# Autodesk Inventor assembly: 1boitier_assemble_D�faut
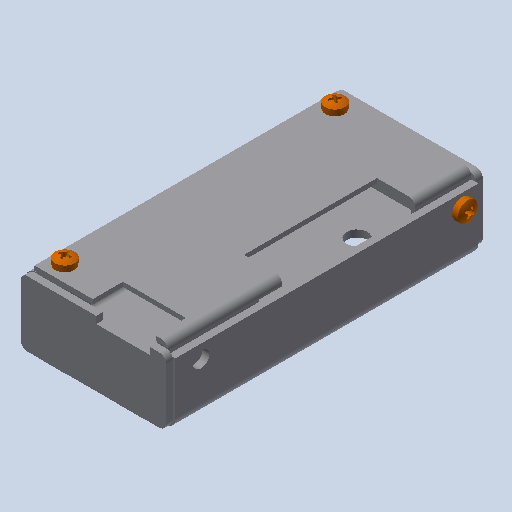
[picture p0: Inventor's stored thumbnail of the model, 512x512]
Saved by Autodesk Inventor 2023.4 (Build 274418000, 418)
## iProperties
Created: 2011-01
Part Number: 1boitier_assemble_D�faut
Document SubType Name: Assembly
Designer: eric
Mass: 73.238 g
Surface Area: 581.356 cm^2
Volume: 73.238 cm^3
Density: 1 g/cm^3
Author: eric
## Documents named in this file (10)
- C:\Users\bruno\Documents\1-Cours-2024-25\TSsI\7-Dynamique\chariot de golf\chariot_de_golf\chariot_de_golf_trolem\1boitier_assemble_Defaut.iam
- C:\Users\bruno\Documents\1-Cours-2024-25\TSsI\7-Dynamique\chariot de golf\chariot_de_golf\chariot_de_golf_trolem\1fond_boitier_Defaut.ipt
- C:\Users\bruno\Documents\1-Cours-2024-25\TSsI\7-Dynamique\chariot de golf\chariot_de_golf\chariot_de_golf_trolem\bead2_Defaut.ipt
- C:\Users\bruno\Documents\1-Cours-2024-25\TSsI\7-Dynamique\chariot de golf\chariot_de_golf\chariot_de_golf_trolem\46Vis CBLZ M5-10.ipt
- C:\Users\bruno\Documents\1-Cours-2024-25\TSsI\7-Dynamique\chariot de golf\chariot_de_golf\chariot_de_golf_trolem\1boitier_Defaut.ipt
- C:\Users\bruno\Documents\1-Cours-2024-25\TSsI\7-Dynamique\chariot de golf\chariot_de_golf\chariot_de_golf_trolem\bead19_Defaut.ipt
- C:\Users\bruno\Documents\1-Cours-2024-25\TSsI\7-Dynamique\chariot de golf\chariot_de_golf\chariot_de_golf_trolem\1plaque_arriere_boitier_Defaut.ipt
- C:\Users\bruno\Documents\1-Cours-2024-25\TSsI\7-Dynamique\chariot de golf\chariot_de_golf\chariot_de_golf_trolem\bead9_Defaut.ipt
- C:\Users\bruno\Documents\1-Cours-2024-25\TSsI\7-Dynamique\chariot de golf\chariot_de_golf\chariot_de_golf_trolem\bead1_Defaut.ipt
- C:\Users\bruno\Documents\1-Cours-2024-25\TSsI\7-Dynamique\chariot de golf\chariot_de_golf\chariot_de_golf_trolem\1plaque_avant_boitier_Defaut.ipt
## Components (11 placed, 9 different names)
1. 1fond_boitier_Defaut:1
2. bead2_Defaut:1
3. 46Vis CBLZ M5-10:1
4. 1boitier_Defaut:1
5. bead19_Defaut:1
6. 46Vis CBLZ M5-10:2
7. 1plaque_arriere_boitier_Defaut:1
8. bead9_Defaut:1
9. bead1_Defaut:1
10. 46Vis CBLZ M5-10:3
11. 1plaque_avant_boitier_Defaut:1
